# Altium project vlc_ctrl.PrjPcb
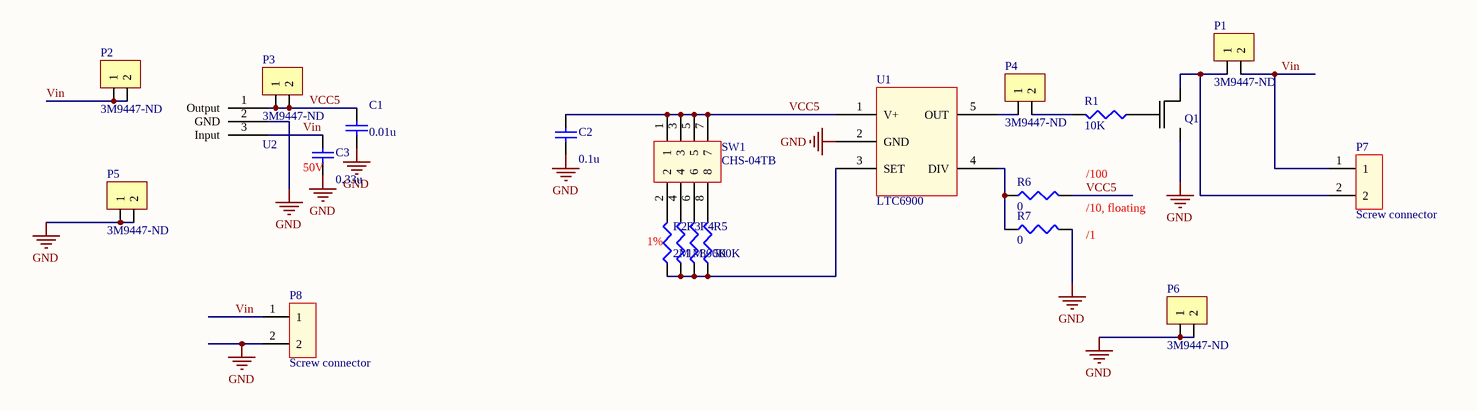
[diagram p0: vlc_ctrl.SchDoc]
1 sheet, 22 parts. Net scope: global (net labels, ports and power ports of the same name join across sheets).
Board file: vlc_ctrl.PcbDoc

## Sheet vlc_ctrl.SchDoc
size Letter

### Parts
C1  value 0.01u  [1608[0603]]  (hidden comment: Cap Semi)
C2  value 0.1u  [1608[0603]]  (hidden comment: Cap Semi)
C3  value 0.33u  [1608[0603]]  (hidden comment: Cap Semi)
P1  Supplier Part Number 1: 3M9447-ND  [1x2 header]  (hidden comment: 1 x 2 header)
P2  Supplier Part Number 1: 3M9447-ND  [1x2 header]  (hidden comment: 1 x 2 header)
P3  Supplier Part Number 1: 3M9447-ND  [1x2 header]  (hidden comment: 1 x 2 header)
P4  Supplier Part Number 1: 3M9447-ND  [1x2 header]  (hidden comment: 1 x 2 header)
P5  Supplier Part Number 1: 3M9447-ND  [1x2 header]  (hidden comment: 1 x 2 header)
P6  Supplier Part Number 1: 3M9447-ND  [1x2 header]  (hidden comment: 1 x 2 header)
P7  Screw connector  [MPT_2position]
P8  Screw connector  [MPT_2position]
Q1  Si2312CDS  [SOT95P250-3N]  (value not drawn)
R1  value 10K  [J1-0603]  (hidden comment: Res3)
R2  value 2M  [J1-0603]  (hidden comment: Res3)
R3  value 1M  [J1-0603]  (hidden comment: Res3)
R4  value 800K  [J1-0603]  (hidden comment: Res3)
R5  value 500K  [J1-0603]  (hidden comment: Res3)
R6  value 0  [J1-0603]  (hidden comment: Res3)
R7  value 0  [J1-0603]  (hidden comment: Res3)
SW1  CHS-04TB  [CHS04TB]
U1  LTC6900  [TSOT23]
U2  LM78L05  [TO92]  (value not drawn)

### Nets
GND: C1.1 C2.1 C3.1 P5.1 P5.2 P6.1 P6.2 P8.2 Q1.2(S) R7.2 U1.2(GND) U2.2(GND)
VCC5: C1.2 C2.2 P3.1 P3.2 R6.2 SW1.1 SW1.3 SW1.5 SW1.7 U1.1(V+) U2.1(Output)
Vin: C3.2 P1.2 P2.1 P2.2 P7.1 P8.1 U2.3(Input)
NetP1_1: P1.1 P7.2 Q1.3(D)
NetP4_1: P4.1 U1.5(OUT)
NetP4_2: P4.2 R1.2
NetQ1_1: Q1.1(G) R1.1
NetR2_1: R2.1 R3.1 R4.1 R5.1 U1.3(SET)
NetR2_2: R2.2 SW1.2
NetR3_2: R3.2 SW1.4
NetR4_2: R4.2 SW1.6
NetR5_2: R5.2 SW1.8
NetR6_1: R6.1 R7.1 U1.4(DIV)

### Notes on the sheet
- (near C3) 50V
- (near R6) /100
- /10, floating
- (near R2) 1%
- /1

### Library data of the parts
C1-C3 = Cap Semi: Capacitor (Semiconductor SIM Model)
P1-P6 = 1 x 2 header: 100 mils standard header
P7 P8 = MPT_2POS: Screw connector 2 positions
Q1 = Si2312CDS: N-Channel 20 V (D-S) MOSFET
R1-R7 = Res3: Resistor
SW1 = CHS-04TB: SLIDE SWITCHES
U1 = LTC6900: Low Power, 1kHz to 20MHz   Resistor Set SOT-23 Oscillator
U2 = LM78L05: LM78LXX Series 3-Terminal Positive Regulators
